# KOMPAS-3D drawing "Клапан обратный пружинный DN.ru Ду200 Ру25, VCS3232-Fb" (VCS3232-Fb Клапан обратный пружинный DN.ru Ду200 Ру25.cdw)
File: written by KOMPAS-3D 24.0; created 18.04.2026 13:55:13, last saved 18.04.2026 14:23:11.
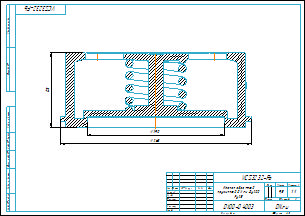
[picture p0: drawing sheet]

Document properties: c3d_UniqueCompID: 071bd168-1a06-425c-849c-e99e84a96128; Наименование: Деталь; Автор: 712; Класс точности: c; Знак неуказанной шероховатости: Шероховатость не задана; Рассекать на разрезах: Да; c3d_UniqueCompID: 071bd168-1a06-425c-849c-e99e84a96128; Наименование: Деталь; Автор: 712; Класс точности: c; Знак неуказанной шероховатости: Шероховатость не задана; Рассекать на разрезах: Да; c3d_UniqueCompID: 071bd168-1a06-425c-849c-e99e84a96128; Наименование: Деталь; Автор: 712; Класс точности: c; Знак неуказанной шероховатости: Шероховатость не задана; Рассекать на разрезах: Да; c3d_UniqueCompID: 071bd168-1a06-425c-849c-e99e84a96128; Наименование: Деталь; Автор: 712; Класс точности: c; Знак неуказанной шероховатости: Шероховатость не задана; Рассекать на разрезах: Да; c3d_UniqueCompID: 071bd168-1a06-425c-849c-e99e84a96128; Наименование: Деталь; Автор: 712; Класс точности: c; Знак неуказанной шероховатости: Шероховатость не задана; Рассекать на разрезах: Да; c3d_UniqueCompID: 071bd168-1a06-425c-849c-e99e84a96128; Наименование: Деталь; Автор: 712; Класс точности: c; Знак неуказанной шероховатости: Шероховатость не задана; Рассекать на разрезах: Да; c3d_UniqueCompID: 071bd168-1a06-425c-849c-e99e84a96128; Наименование: Деталь; Автор: 712; Класс точности: c; Знак неуказанной шероховатости: Шероховатость не задана; Рассекать на разрезах: Да; c3d_UniqueCompID: 071bd168-1a06-425c-849c-e99e84a96128; Наименование: Деталь; Автор: 712; Класс точности: c; Знак неуказанной шероховатости: Шероховатость не задана; Рассекать на разрезах: Да; c3d_UniqueCompID: 071bd168-1a06-425c-849c-e99e84a96128; Наименование: Деталь; Автор: 712; Класс точности: c; Знак неуказанной шероховатости: Шероховатость не задана; Рассекать на разрезах: Да; c3d_UniqueCompID: 071bd168-1a06-425c-849c-e99e84a96128; Наименование: Деталь; Автор: 712; Класс точности: c; Знак неуказанной шероховатости: Шероховатость не задана; Рассекать на разрезах: Да; c3d_UniqueCompID: 071bd168-1a06-425c-849c-e99e84a96128; Наименование: Деталь; Автор: 712; Класс точности: c; Знак неуказанной шероховатости: Шероховатость не задана; Рассекать на разрезах: Да; c3d_UniqueCompID: 071bd168-1a06-425c-849c-e99e84a96128; Наименование: Деталь; Автор: 712; Класс точности: c; Знак неуказанной шероховатости: Шероховатость не задана; Рассекать на разрезах: Да; Автор: 712; Форматы листов документа: A3; Полное имя файла: VCS3232-Fb Клапан обратный пружинный DN.ru Ду200 Ру25.m3d; Масса: 9.5; Наименование: Клапан обратный пружинный DN.ru Ду200 Ру25; Количество листов документа: 1; Примечание: D100-04003

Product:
- Component: Пружина 1086-1155 ГОСТ 18793-80  | qty 1  | additional columns: 3953604318-4147491677-0; Деталь; Пользователь Windows; c; Шероховатость не задана; Да; Сталь 10  ГОСТ 1050-88; source file: Деталь_3.m3d
- Body: Тело 1  | qty 1
    Масса: 13.506002
- Part/product: Клапан обратный пружинный DN.ru Ду200 Ру25  | designation VCS3232-Fb
    Масса: 9.5
    Раздел спецификации: Прочие изделия
    Примечание: D100-04003
    additional columns: 071bd168-1a06-425c-849c-e99e84a96128; Деталь; 712; c; Шероховатость не задана; Да

Views: Вид 1, Местный разрез 1, Спереди
Referenced files in C:\Users\712\Desktop\Новая папка (4)\: VCS3232-Fb Клапан обратный пружинный DN.ru Ду15 Ру40.m3d, VCS3232-Fb Клапан обратный пружинный DN.ru Ду200 Ру25.m3d, VCS3232-Fb Клапан обратный пружинный DN.ru Ду15 Ру40.cdw
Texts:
  VCS3232-Fb
  Клапан обратный
  пружинный DN.ru Ду200
  Ру25
  Клапан обратный пружинный DN.ru Ду200 Ру25
  VCS3232-Fb Клапан обратный пружинный DN.ru Ду200 Ру25
Dimensions and other numbers on the sheet: 0; 3; 2; 4; 263; 190; 103; 1:1; 1; 9,5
